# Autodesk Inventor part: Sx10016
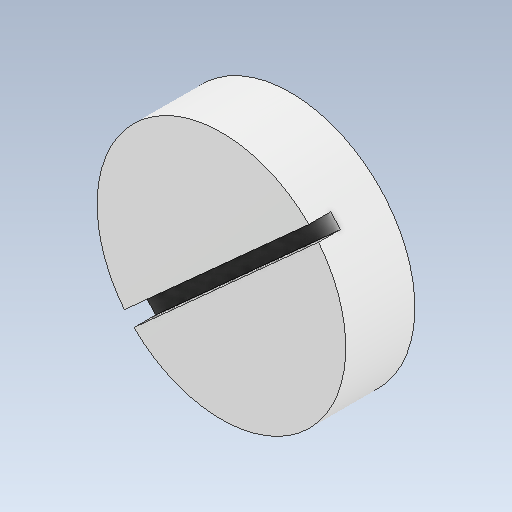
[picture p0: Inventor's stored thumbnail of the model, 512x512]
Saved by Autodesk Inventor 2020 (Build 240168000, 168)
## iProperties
Created: 2021-02
Part Number: Sx10016
Material: Generico
Document SubType Name: Modeling
Designer: zambolin
Density: 1 g/cm^3
Appearance: Default
Author: zambolin
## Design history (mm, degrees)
feature "Solido2"
node "Solido1"
